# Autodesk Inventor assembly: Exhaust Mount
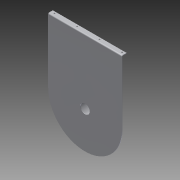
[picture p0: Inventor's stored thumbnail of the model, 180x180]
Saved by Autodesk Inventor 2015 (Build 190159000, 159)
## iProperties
Created: 2007-02
Part Number: Exhaust Mount
Document SubType Name: Weldment
Designer: Autodesk, Inc.
Weld Material: Welded Aluminum-6061
Mass: 1876.1 g
Surface Area: 4672.2 cm^2
Volume: 692.289 cm^3
Density: 2.71 g/cm^3
Author: Autodesk, Inc.
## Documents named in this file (4)
- C:\Users\Public\Documents\Autodesk\Inventor 2015\Samples\Models\Assemblies\Blower\Components\Exhaust Mount.iam
- C:\Users\Public\Documents\Autodesk\Inventor 2015\Samples\Models\Assemblies\Blower\Components\Exhaust Offset.ipt
- C:\Users\Public\Documents\Autodesk\Inventor 2015\Samples\Models\Assemblies\Blower\Components\Gusset.ipt
- C:\Users\Public\Documents\Autodesk\Inventor 2015\Samples\Models\Assemblies\Blower\Components\Exhaust_02.ipt
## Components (6 placed, 3 different names)
1. Exhaust Offset:2 — Mate:4, Angle:1
2. Exhaust Port:7
3. Gusset:1 — Mate:4, Angle:1
4. Gusset:2
5. Gusset:5
6. Gusset:6
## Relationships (2: Mate 1, Angle 1)
- Mate:4: Exhaust Offset:2 ↔ Gusset:1
- Angle:1: Exhaust Offset:2 ↔ Gusset:1
